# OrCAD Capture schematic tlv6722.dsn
size A
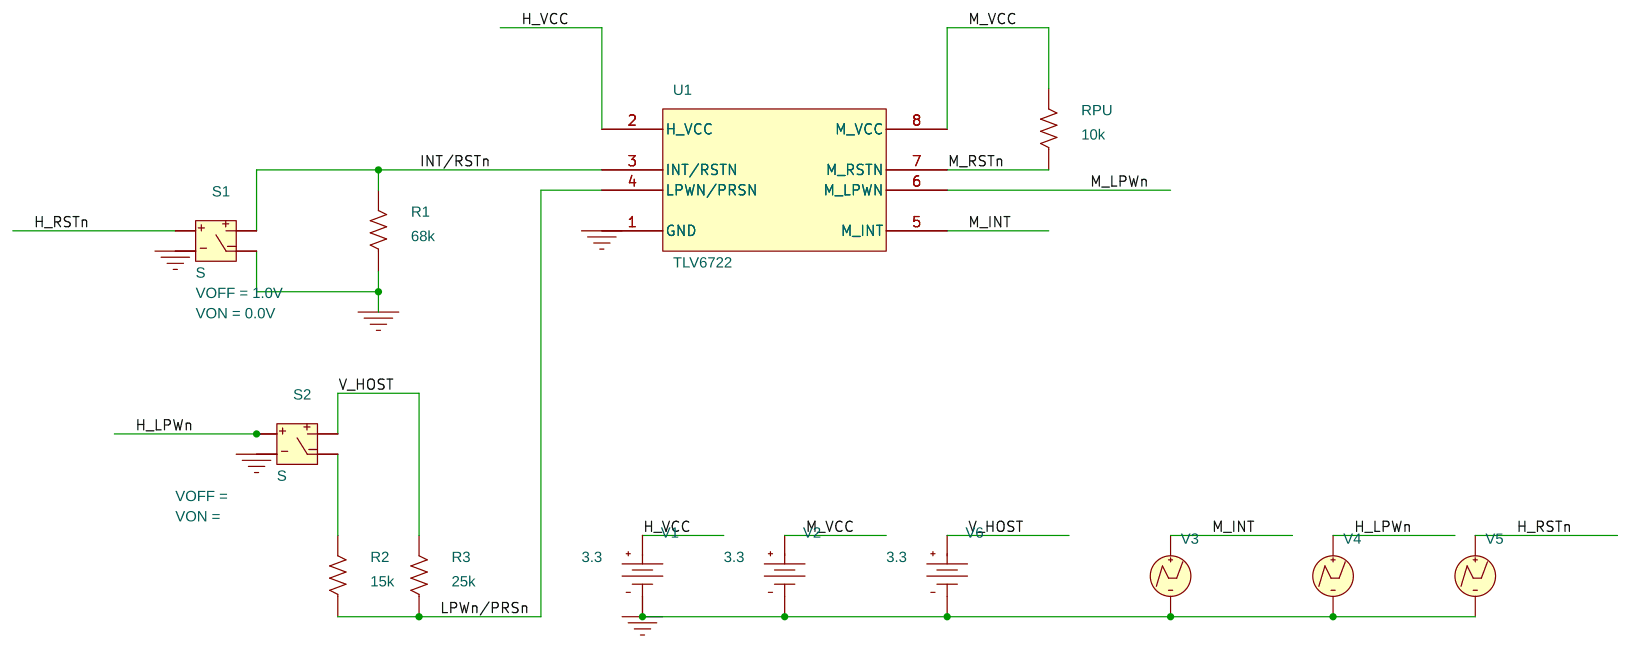
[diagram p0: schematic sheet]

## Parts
R1  68k  [AXRC05]
R2  15k  [AXRC05]
R3  25k  [AXRC05]
RPU  10k  [AXRC05]
S1  S
S2  S
U1  TLV6722
V1  VDC
V2  VDC
V3  VPWL
V4  VPWL
V5  VPWL
V6  VDC

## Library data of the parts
R1-R3 RPU = R
S1 = S: VOFF: 1.0V; VON: 0.0V
S2 = S
U1 = TLV6722
V1 V2 V6 = VDC: DC: 3.3
V3 = VPWL: DC: 0; T1: 0; T2: 150u; T3: 150.001u; T4: 250u; T5: 250.001u; V1: 0; V2: 0; V3: 3.3; V4: 3.3; V5: 0
V4 = VPWL: T1: 0; T2: 450u; T3: 450.001u; T4: 550u; T5: 550.001u; V1: 1; V2: 1; V3: 0; V4: 0; V5: 1
V5 = VPWL: T1: 0; T2: 750u; T3: 750.001u; T4: 850u; T5: 850.001u; V1: 1; V2: 1; V3: 0; V4: 0; V5: 1

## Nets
0: R1.1 S1.1(2) S1.3(4) S2.1(2) U1.1(GND) V1.1(-) V2.1(-) V3.2(-) V4.2(-) V5.2(-) V6.1(-)
H_LPWn: S2.0(1) V4.1(+)
H_RSTn: S1.0(1) V5.1(+)
H_VCC: U1.2(H_VCC) V1.0(+)
INT/RSTn: R1.2 S1.2(3) U1.3(INT/RSTN)
LPWn/PRSn: R2.1 R3.1 U1.4(LPWN/PRSN)
M_INT: U1.5(M_INT) V3.1(+)
M_LPWn: U1.6(M_LPWN)
M_RSTn: RPU.1 U1.7(M_RSTN)
M_VCC: RPU.2 U1.8(M_VCC) V2.0(+)
V_HOST: R3.2 S2.2(3) V6.0(+)
N00592: R2.2 S2.3(4)
